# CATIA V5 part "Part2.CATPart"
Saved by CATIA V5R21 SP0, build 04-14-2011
Part number: Part2
Bounding box of the stored display mesh (mm): x -15 to 15, y -15 to 15, z 0 to 20
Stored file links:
  D:\CATIA V5R21 E-RESOURCES\CATIA-V5R21\catia-v5r21-prt\c16-catia-v5r20-prt\Roll Curve Joint-(Fig16-43)\CAT_V5R21_Part2.CATPart
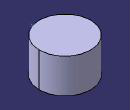
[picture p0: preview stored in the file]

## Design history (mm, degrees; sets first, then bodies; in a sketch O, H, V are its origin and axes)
Body1 (main body)
  Sketch1 on xy-plane, origin (0, 0, 0), H (1, 0, 0), V (0, 1, 0)
    circle A1 centre (0, 0) radius 15
    radius A1 = 15
  Pad1: profile Sketch1, direction (0, 0, 1), length 20
  Point1: type OnCurve, Support edge [face of Pad1 from Sketch1.A1 | end face of Pad1], RefPoint {extremum Reference edge [face of Pad1 from Sketch1.A1 | end face of Pad1], Direction (1, 2, 3)}, Length 58.791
